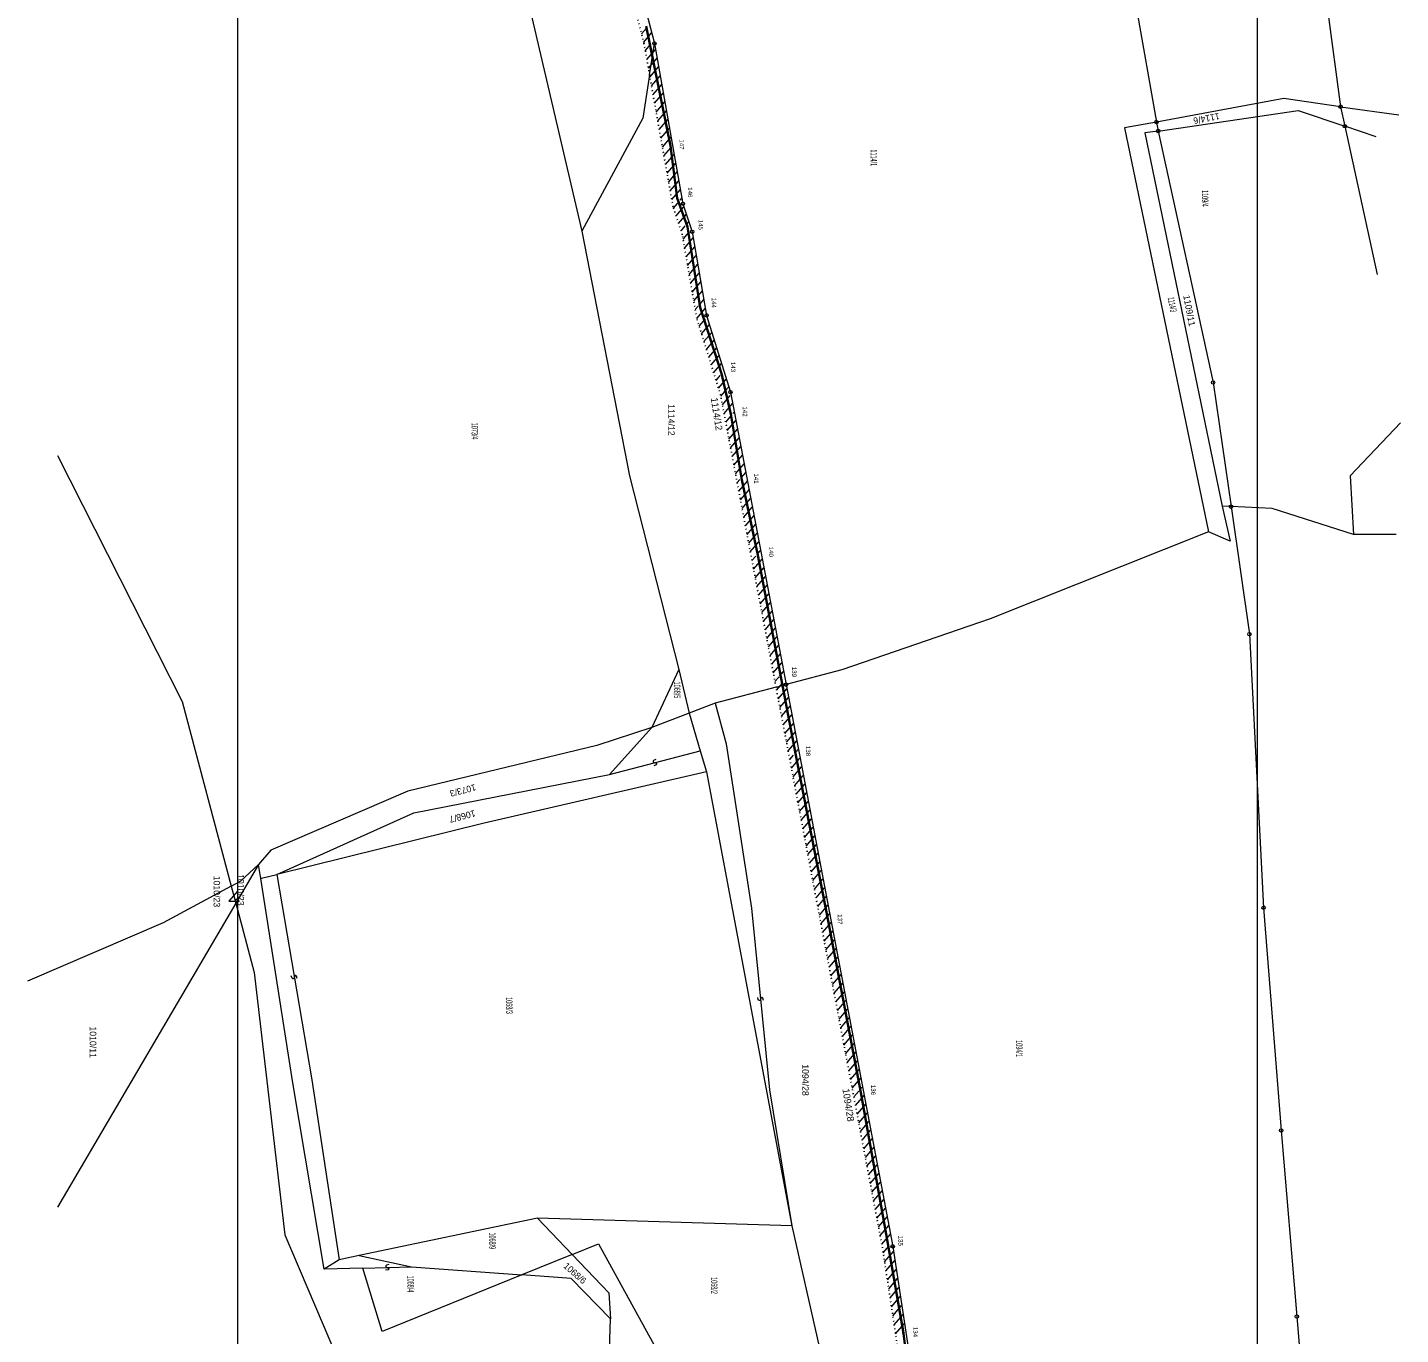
# Model space of a CAD drawing. Extents: x -687355 to -686912, y -958376 to -957235.
# Drawn here: x -687349.1 to -686949.3, y -958143.7 to -957763.2 of the extents above; entities that cross this region are included whole.
import ezdxf
from ezdxf.enums import TextEntityAlignment as Align

# ---------------------------------------------------------------- set-up
doc = ezdxf.new("R2010")
doc.units = 0
doc.header["$LTSCALE"] = 0.76
doc.linetypes.add('DOTTED', pattern=[1.5, 0.3, -1.2])
for name, color, linetype, lineweight in [('1', 7, 'Continuous', 13), ('16', 7, 'Continuous', 13), ('2', 7, 'Continuous', 13), ('28', 7, 'Continuous', 13)]:
    doc.layers.add(name, color=color, linetype=linetype, lineweight=lineweight)
doc.layers.add('14', color=7, linetype='Continuous')

msp = doc.modelspace()

# ---------------------------------------------------------------- linework, layer by layer
at = {"layer": '1', "linetype": 'DOTTED', "lineweight": 25}
for p, q in [((-687169.6, -957767.785), (-687196.769, -957663.253)), ((-687167.989, -957777), (-687169.6, -957767.785)), ((-687161.144, -957815.361), (-687167.989, -957777)), ((-687158.446, -957823.516), (-687161.144, -957815.361)), ((-687154.257, -957847.827), (-687158.446, -957823.516)), ((-687147.315, -957870.163), (-687154.257, -957847.827)), ((-687131.151, -957955.283), (-687147.315, -957870.163)), ((-687100.153, -958118.538), (-687131.151, -957955.283)), ((-687090.903, -958179.389), (-687100.153, -958118.538))]:
    msp.add_line(p, q, dxfattribs=at)
at = {"layer": '1'}
for p, q in [((-687193.4, -957662.8), (-687166.57, -957767.82)), ((-687220.92, -957680.58), (-687187.67, -957822.53)), ((-687028.25, -957746), (-687020.41, -957790.71)), ((-687170.305, -957765.071), (-687168.904, -957763.43)), ((-687169.692, -957767.432), (-687167.365, -957764.707)), ((-687169.22, -957769.959), (-687167.57, -957768.027)), ((-687166.57, -957767.82), (-687158.27, -957814.5)), ((-687168.773, -957772.515), (-687166.258, -957769.571)), ((-687168.326, -957775.072), (-687165.805, -957772.12)), ((-687167.877, -957777.626), (-687165.352, -957774.669)), ((-687167.989, -957777), (-687169.94, -957789.62)), ((-687167.423, -957780.173), (-687164.898, -957777.218)), ((-687166.968, -957782.72), (-687164.445, -957779.766)), ((-687166.514, -957785.268), (-687163.992, -957782.315)), ((-687166.059, -957787.815), (-687163.539, -957784.864)), ((-687165.605, -957790.363), (-687163.086, -957787.413)), ((-686966.78, -957786.25), (-686949.85, -957788.66)), ((-687169.94, -957789.62), (-687187.67, -957822.53)), ((-687165.15, -957792.91), (-687162.632, -957789.962)), ((-687164.696, -957795.457), (-687162.179, -957792.511)), ((-687020.41, -957790.71), (-687019.9, -957793.33)), ((-686956.43, -957795.03), (-686965.54, -957791.95)), ((-687164.241, -957798.005), (-687161.726, -957795.06)), ((-687019.9, -957793.33), (-687003.91, -957866.54)), ((-687163.787, -957800.552), (-687161.787, -957798.211)), ((-687163.332, -957803.099), (-687160.82, -957800.158)), ((-687162.878, -957805.647), (-687160.366, -957802.706)), ((-687162.423, -957808.194), (-687159.913, -957805.255)), ((-687161.969, -957810.742), (-687159.46, -957807.804)), ((-687161.514, -957813.289), (-687159.007, -957810.353)), ((-687159.064, -957813.5), (-687158.554, -957812.902)), ((-687161.007, -957815.775), (-687159.27, -957813.74)), ((-687160.273, -957817.995), (-687158.142, -957815.5)), ((-687159.539, -957820.214), (-687157.261, -957817.548)), ((-687157.225, -957820.585), (-687156.526, -957819.767)), ((-687158.804, -957822.434), (-687157.566, -957820.985)), ((-687158.22, -957824.829), (-687156.57, -957822.897)), ((-687157.778, -957827.392), (-687155.261, -957824.445)), ((-687157.337, -957829.954), (-687154.82, -957827.007)), ((-687156.895, -957832.517), (-687154.378, -957829.569)), ((-687156.453, -957835.08), (-687153.936, -957832.132)), ((-687156.012, -957837.642), (-687153.494, -957834.694)), ((-687155.57, -957840.205), (-687153.052, -957837.256)), ((-687155.129, -957842.767), (-687152.61, -957839.818)), ((-687154.687, -957845.33), (-687153.813, -957844.306)), ((-687153.639, -957844.103), (-687152.168, -957842.38)), ((-687154.239, -957847.885), (-687151.726, -957844.942)), ((-687153.537, -957850.142), (-687151.716, -957848.01)), ((-687151.37, -957847.01), (-687144.43, -957869.34)), ((-687152.836, -957852.4), (-687150.532, -957849.703)), ((-687152.134, -957854.658), (-687149.831, -957851.961)), ((-687151.432, -957856.916), (-687149.129, -957854.219)), ((-687150.73, -957859.174), (-687148.427, -957856.477)), ((-687150.029, -957861.432), (-687147.725, -957858.735)), ((-687149.327, -957863.69), (-687147.024, -957860.993)), ((-687148.625, -957865.948), (-687147.442, -957864.562)), ((-687147.923, -957868.206), (-687145.62, -957865.509)), ((-687147.251, -957870.498), (-687145.43, -957868.365)), ((-687145.408, -957868.34), (-687144.918, -957867.767)), ((-687003.91, -957866.54), (-686998.68, -957902.7)), ((-687146.773, -957873.018), (-687144.486, -957870.34)), ((-687146.295, -957875.537), (-687143.806, -957872.623)), ((-687144.43, -957869.34), (-687128.25, -957954.52)), ((-687145.816, -957878.056), (-687144.358, -957876.349)), ((-687143.697, -957875.575), (-687143.327, -957875.142)), ((-687145.338, -957880.576), (-687142.849, -957877.662)), ((-687144.859, -957883.095), (-687142.37, -957880.181)), ((-687144.381, -957885.615), (-687141.892, -957882.7)), ((-687143.902, -957888.134), (-687141.413, -957885.219)), ((-687143.424, -957890.653), (-687140.935, -957887.739)), ((-687142.946, -957893.173), (-687140.456, -957890.258)), ((-687141.267, -957894.286), (-687139.978, -957892.777)), ((-687142.467, -957895.692), (-687141.667, -957894.756)), ((-687141.989, -957898.211), (-687139.499, -957895.296)), ((-687141.51, -957900.731), (-687139.02, -957897.816)), ((-687141.032, -957903.25), (-687138.542, -957900.335)), ((-687140.553, -957905.77), (-687138.063, -957902.854)), ((-686998.68, -957902.7), (-687001.22, -957902.6)), ((-686998.68, -957902.7), (-686993.32, -957939.83)), ((-687140.075, -957908.289), (-687137.585, -957905.373)), ((-687139.597, -957910.808), (-687137.106, -957907.893)), ((-687139.118, -957913.328), (-687136.628, -957910.412)), ((-686950.64, -957910.79), (-686963, -957910.76)), ((-687138.64, -957915.847), (-687136.149, -957912.931)), ((-687136.355, -957916.251), (-687135.671, -957915.45)), ((-687138.161, -957918.366), (-687137.063, -957917.081)), ((-687137.683, -957920.886), (-687135.192, -957917.97)), ((-687137.204, -957923.405), (-687134.714, -957920.489)), ((-687136.726, -957925.924), (-687134.235, -957923.008)), ((-687136.248, -957928.444), (-687133.757, -957925.527)), ((-687135.769, -957930.963), (-687133.278, -957928.047)), ((-687135.291, -957933.483), (-687132.8, -957930.566)), ((-687134.812, -957936.002), (-687132.321, -957933.085)), ((-687134.334, -957938.521), (-687131.842, -957935.604)), ((-687133.855, -957941.041), (-687131.364, -957938.124)), ((-687133.377, -957943.56), (-687130.885, -957940.643)), ((-686993.32, -957939.83), (-686989.2, -958019.47)), ((-687132.899, -957946.079), (-687130.407, -957943.162)), ((-687132.42, -957948.599), (-687129.928, -957945.681)), ((-687131.942, -957951.118), (-687129.45, -957948.201)), ((-687159.43, -957950.14), (-687167.34, -957967)), ((-687131.463, -957953.637), (-687130.262, -957952.231)), ((-687130.143, -957952.092), (-687128.971, -957950.72)), ((-687112.04, -957950.25), (-687128.25, -957954.52)), ((-687131.151, -957955.283), (-687148.92, -957959.96)), ((-687130.985, -957956.157), (-687129.25, -957954.125)), ((-687130.506, -957958.676), (-687128.014, -957955.758)), ((-687148.92, -957959.96), (-687156.44, -957962.83)), ((-687130.028, -957961.196), (-687127.536, -957958.278)), ((-687129.55, -957963.715), (-687127.057, -957960.797)), ((-687156.44, -957962.83), (-687167.34, -957967)), ((-687129.071, -957966.235), (-687126.579, -957963.316)), ((-687179.65, -957980.68), (-687167.34, -957967)), ((-687128.593, -957968.754), (-687126.1, -957965.836)), ((-687128.115, -957971.273), (-687125.622, -957968.355)), ((-687127.636, -957973.793), (-687125.144, -957970.874)), ((-687179.65, -957980.68), (-687153.22, -957973.76)), ((-687127.158, -957976.312), (-687126.087, -957975.059)), ((-687126.679, -957978.832), (-687124.187, -957975.913)), ((-687125.169, -957973.984), (-687124.665, -957973.394)), ((-687126.201, -957981.351), (-687123.708, -957978.432)), ((-687125.723, -957983.871), (-687123.23, -957980.952)), ((-687125.244, -957986.39), (-687122.751, -957983.471)), ((-687124.766, -957988.91), (-687122.273, -957985.99)), ((-687124.288, -957991.429), (-687121.794, -957988.51)), ((-687123.809, -957993.948), (-687121.316, -957991.029)), ((-687123.331, -957996.468), (-687120.837, -957993.548)), ((-687122.852, -957998.987), (-687120.359, -957996.068)), ((-687122.374, -958001.507), (-687119.881, -957998.587)), ((-687121.896, -958004.026), (-687119.402, -958001.107)), ((-687121.417, -958006.546), (-687118.924, -958003.626)), ((-687281.19, -958010.95), (-687281.83, -958006.9)), ((-687120.939, -958009.065), (-687118.445, -958006.145)), ((-687120.461, -958011.584), (-687117.967, -958008.665)), ((-687119.982, -958014.104), (-687117.488, -958011.184)), ((-687287.95, -958014.69), (-687290.43, -958017.52)), ((-687119.504, -958016.623), (-687117.01, -958013.703)), ((-687119.025, -958019.143), (-687116.531, -958016.223)), ((-687288.45, -958018.19), (-687340.4, -958106.69)), ((-687118.547, -958021.662), (-687116.053, -958018.742)), ((-686989.2, -958019.47), (-686984.09, -958084.32)), ((-687118.069, -958024.182), (-687115.574, -958021.261)), ((-687117.59, -958026.701), (-687115.096, -958023.781)), ((-687117.112, -958029.22), (-687114.618, -958026.3)), ((-687116.634, -958031.74), (-687114.139, -958028.819)), ((-687116.155, -958034.259), (-687113.661, -958031.339)), ((-687115.677, -958036.779), (-687113.182, -958033.858)), ((-687115.198, -958039.298), (-687112.704, -958036.377)), ((-687114.72, -958041.818), (-687112.225, -958038.897)), ((-687114.242, -958044.337), (-687111.747, -958041.416)), ((-687113.763, -958046.856), (-687111.268, -958043.935)), ((-687113.285, -958049.376), (-687110.79, -958046.455)), ((-687112.807, -958051.895), (-687110.312, -958048.974)), ((-687112.328, -958054.415), (-687109.833, -958051.493)), ((-687111.85, -958056.934), (-687109.355, -958054.013)), ((-687111.371, -958059.454), (-687108.876, -958056.532)), ((-687110.893, -958061.973), (-687108.398, -958059.051)), ((-687110.415, -958064.492), (-687107.919, -958061.571)), ((-687109.936, -958067.012), (-687107.441, -958064.09)), ((-687109.458, -958069.531), (-687106.962, -958066.609)), ((-687108.98, -958072.051), (-687106.484, -958069.129)), ((-687106.915, -958072.713), (-687106.005, -958071.648)), ((-687108.501, -958074.57), (-687107.093, -958072.922)), ((-687108.023, -958077.09), (-687105.527, -958074.167)), ((-687107.544, -958079.609), (-687105.049, -958076.687)), ((-687107.066, -958082.128), (-687104.57, -958079.206)), ((-687106.588, -958084.648), (-687104.092, -958081.725)), ((-687106.109, -958087.167), (-687103.613, -958084.245)), ((-686984.09, -958084.32), (-686979.52, -958138.48)), ((-687105.631, -958089.687), (-687103.135, -958086.764)), ((-687105.153, -958092.206), (-687102.656, -958089.284)), ((-687104.674, -958094.726), (-687102.178, -958091.803)), ((-687104.196, -958097.245), (-687101.699, -958094.322)), ((-687103.717, -958099.765), (-687101.221, -958096.842)), ((-687103.239, -958102.284), (-687100.742, -958099.361)), ((-687102.761, -958104.803), (-687100.264, -958101.88)), ((-687102.282, -958107.323), (-687099.786, -958104.4)), ((-687101.804, -958109.842), (-687099.307, -958106.919)), ((-687101.325, -958112.362), (-687098.829, -958109.438)), ((-687100.847, -958114.881), (-687098.35, -958111.958)), ((-687100.369, -958117.401), (-687097.872, -958114.477)), ((-687099.935, -958119.972), (-687098.19, -958117.929)), ((-687099.537, -958122.586), (-687096.961, -958119.57)), ((-687251.42, -958124.38), (-687262.69, -958124.68)), ((-687251.42, -958124.38), (-687237.26, -958124.01)), ((-687099.14, -958125.201), (-687096.564, -958122.184)), ((-687098.743, -958127.815), (-687096.167, -958124.799)), ((-687098.345, -958130.429), (-687095.769, -958127.413)), ((-687097.948, -958133.043), (-687095.372, -958130.027)), ((-687097.551, -958135.658), (-687094.975, -958132.642)), ((-687097.153, -958138.272), (-687094.577, -958135.256)), ((-687096.756, -958140.886), (-687094.18, -958137.87)), ((-687096.358, -958143.501), (-687093.782, -958140.484)), ((-686979.52, -958138.48), (-686976.35, -958176.02))]:
    msp.add_line(p, q, dxfattribs=at)
for points in [[(-687287.96, -957310.331), (-687287.96, -958310.331), (-686990.96, -958310.331), (-686990.96, -957310.331)], [(-687161.778, -957797.511), (-687161.781, -957797.711), (-687161.981, -957797.708), (-687161.978, -957797.508)], [(-687159.858, -957812.811), (-687159.861, -957813.011), (-687160.061, -957813.008), (-687160.058, -957812.808)], [(-687156.868, -957821.091), (-687156.871, -957821.291), (-687157.071, -957821.288), (-687157.068, -957821.088)], [(-687153.118, -957844.611), (-687153.121, -957844.811), (-687153.321, -957844.808), (-687153.318, -957844.608)], [(-687146.888, -957863.871), (-687146.891, -957864.071), (-687147.091, -957864.068), (-687147.088, -957863.868)], [(-687144.198, -957875.651), (-687144.201, -957875.851), (-687144.401, -957875.848), (-687144.398, -957875.648)], [(-687140.968, -957894.791), (-687140.971, -957894.991), (-687141.171, -957894.988), (-687141.168, -957894.788)], [(-687136.358, -957916.751), (-687136.361, -957916.951), (-687136.561, -957916.948), (-687136.558, -957916.748)], [(-687129.568, -957952.601), (-687129.571, -957952.801), (-687129.771, -957952.798), (-687129.768, -957952.598)], [(-687125.378, -957974.481), (-687125.381, -957974.681), (-687125.581, -957974.678), (-687125.578, -957974.478)], [(-687115.868, -958023.171), (-687115.871, -958023.371), (-687116.071, -958023.368), (-687116.068, -958023.168)], [(-687106.398, -958073.221), (-687106.401, -958073.421), (-687106.601, -958073.418), (-687106.598, -958073.218)], [(-687098.478, -958117.101), (-687098.481, -958117.301), (-687098.681, -958117.298), (-687098.678, -958117.098)], [(-687093.988, -958143.291), (-687093.991, -958143.491), (-687094.191, -958143.488), (-687094.188, -958143.288)]]:
    msp.add_lwpolyline(points, close=True, dxfattribs=at)
for points in [[(-686985.76, -957644.49), (-686966.78, -957786.25), (-686965.54, -957791.95), (-686956.11, -957835.14)], [(-686966.78, -957786.25), (-686983.35, -957783.9), (-687020.41, -957790.71)], [(-687019.9, -957793.33), (-686979.14, -957787.35), (-686965.54, -957791.95)], [(-687020.41, -957790.71), (-687029.66, -957792.41), (-687005.25, -957910.06), (-687068.79, -957935.37), (-687112.04, -957950.25)], [(-687019.9, -957793.33), (-687023.73, -957793.89), (-687001.22, -957902.6), (-686998.9, -957912.74), (-687005.25, -957910.06)], [(-687158.27, -957814.5), (-687155.57, -957822.66), (-687151.37, -957847.01)], [(-687187.67, -957822.53), (-687173.85, -957893.76), (-687159.43, -957950.14)], [(-686949.33, -957878.3), (-686963.99, -957893.77), (-686963, -957910.76)], [(-687340.35, -957887.8), (-687304.03, -957959.4), (-687289.77, -958013.23)], [(-686963, -957910.76), (-686986.69, -957903.2), (-686998.68, -957902.7)], [(-687159.43, -957950.14), (-687156.44, -957962.83), (-687153.22, -957973.76), (-687151.4, -957979.95), (-687126.55, -958112.05)], [(-687128.25, -957954.52), (-687097.19, -958118.07), (-687087.95, -958178.86)], [(-687148.92, -957959.96), (-687145.67, -957971.79), (-687138.27, -958019.65), (-687133.01, -958072.48), (-687126.55, -958112.05)], [(-687167.34, -957967), (-687183.33, -957972.2), (-687238.37, -957985.54), (-687278.29, -958002.75), (-687281.83, -958006.9)], [(-687166.153, -957976.319), (-687166.805, -957976.593), (-687166.948, -957976.837), (-687166.897, -957977.031), (-687166.653, -957977.173), (-687166.216, -957977.266), (-687165.972, -957977.408), (-687165.921, -957977.602), (-687166.064, -957977.846), (-687166.716, -957978.12)], [(-687151.4, -957979.95), (-687216.09, -957994.84), (-687276.52, -958009.83)], [(-687276.52, -958009.83), (-687236.64, -957991.89), (-687179.65, -957980.68)], [(-687289.77, -958013.23), (-687287.04, -958011.77), (-687281.83, -958006.9), (-687288.45, -958018.19)], [(-687252.52, -958120.76), (-687258.33, -958121.99), (-687262.69, -958124.68), (-687271.83, -958070.43), (-687281.19, -958010.95), (-687280.54, -958010.79), (-687276.52, -958009.83)], [(-687276.52, -958009.83), (-687266.29, -958069.56), (-687258.33, -958121.99)], [(-687289.77, -958013.23), (-687309.59, -958023.89), (-687349.1, -958040.84)], [(-687289.77, -958013.23), (-687288.45, -958018.19), (-687283.12, -958038.32), (-687274.12, -958114.74), (-687252.46, -958165.73), (-687201.83, -958253.91)], [(-687270.532, -958040.052), (-687270.748, -958039.379), (-687270.979, -958039.216), (-687271.176, -958039.25), (-687271.34, -958039.48), (-687271.469, -958039.909), (-687271.633, -958040.139), (-687271.83, -958040.173), (-687272.061, -958040.01), (-687272.277, -958039.337)], [(-687134.794, -958046.483), (-687134.963, -958045.796), (-687135.182, -958045.617), (-687135.381, -958045.637), (-687135.56, -958045.856), (-687135.719, -958046.273), (-687135.898, -958046.492), (-687136.097, -958046.512), (-687136.316, -958046.333), (-687136.485, -958045.646)], [(-687126.55, -958112.05), (-687200.63, -958109.82), (-687252.52, -958120.76)], [(-687200.63, -958109.82), (-687190.47, -958120.44), (-687205.15, -958126.39)], [(-687126.55, -958112.05), (-687118.53, -958147.73), (-687109.71, -958175.34), (-687103.96, -958208.19), (-687099.17, -958221.16)], [(-687252.52, -958120.76), (-687237.26, -958124.01), (-687205.15, -958126.39)], [(-687190.47, -958120.44), (-687182.85, -958117.36), (-687157.48, -958163.42)], [(-687190.47, -958120.44), (-687179.8, -958131.58), (-687179.37, -958139.16)], [(-687205.15, -958126.39), (-687245.82, -958142.85), (-687251.42, -958124.38)], [(-687243.861, -958123.382), (-687244.558, -958123.5), (-687244.752, -958123.705), (-687244.747, -958123.905), (-687244.542, -958124.1), (-687244.137, -958124.289), (-687243.932, -958124.484), (-687243.927, -958124.684), (-687244.121, -958124.889), (-687244.818, -958125.007)], [(-687179.37, -958139.16), (-687190.79, -958127.45), (-687205.15, -958126.39)], [(-687157.48, -958163.42), (-687167.35, -958172.3), (-687180.29, -958168.41), (-687179.37, -958139.16)]]:
    msp.add_lwpolyline(points, dxfattribs=at)
for centre, radius in [((-687166.57, -957767.82), 0.5), ((-687166.57, -957767.82), 0.01), ((-686966.78, -957786.25), 0.5), ((-686966.78, -957786.25), 0.01), ((-687020.41, -957790.71), 0.5), ((-687020.41, -957790.71), 0.01), ((-687019.9, -957793.33), 0.5), ((-686965.54, -957791.95), 0.5), ((-686965.54, -957791.95), 0.01), ((-687019.9, -957793.33), 0.01), ((-687158.27, -957814.5), 0.5), ((-687158.27, -957814.5), 0.01), ((-687155.57, -957822.66), 0.5), ((-687155.57, -957822.66), 0.01), ((-687151.37, -957847.01), 0.5), ((-687151.37, -957847.01), 0.01), ((-687144.43, -957869.34), 0.5), ((-687003.91, -957866.54), 0.5), ((-687003.91, -957866.54), 0.01), ((-687144.43, -957869.34), 0.01), ((-686998.68, -957902.7), 0.5), ((-686998.68, -957902.7), 0.01), ((-686993.32, -957939.83), 0.5), ((-686993.32, -957939.83), 0.01), ((-687128.25, -957954.52), 0.5), ((-687128.25, -957954.52), 0.01), ((-686989.2, -958019.47), 0.5), ((-686989.2, -958019.47), 0.01), ((-686984.09, -958084.32), 0.5), ((-686984.09, -958084.32), 0.01), ((-687097.19, -958118.07), 0.5), ((-687097.19, -958118.07), 0.01), ((-686979.52, -958138.48), 0.5), ((-686979.52, -958138.48), 0.01)]:
    msp.add_circle(centre, radius, dxfattribs=at)
at = {"layer": '16'}
msp.add_line((-687287.43, -958017.52), (-687288.43, -958018.02), dxfattribs=at)
msp.add_lwpolyline([(-687290.43, -958017.52), (-687287.43, -958017.52), (-687288.43, -958017.02)], dxfattribs=at)
at = {"layer": '2'}
for p, q in [((-687167.989, -957777), (-687166.57, -957767.82)), ((-687131.151, -957955.283), (-687128.25, -957954.52))]:
    msp.add_line(p, q, dxfattribs=at)
at = {"layer": '2', "lineweight": 35}
msp.add_lwpolyline([(-687079.355, -958217.582), (-687078.27, -958216.4), (-687079.21, -958212.07), (-687089.1, -958178.68), (-687091.56, -958163.84), (-687094.09, -958143.39), (-687098.58, -958117.2), (-687106.5, -958073.32), (-687115.97, -958023.27), (-687125.48, -957974.58), (-687129.67, -957952.7), (-687136.46, -957916.85), (-687141.07, -957894.89), (-687144.3, -957875.75), (-687146.99, -957863.97), (-687153.22, -957844.71), (-687156.97, -957821.19), (-687159.96, -957812.91), (-687161.88, -957797.61), (-687168.94, -957762.83)], dxfattribs=at)
at = {"layer": '28'}
for centre, radius in [((-687166.57, -957767.82), 0.5), ((-687166.57, -957767.82), 0.01), ((-686966.78, -957786.25), 0.5), ((-686966.78, -957786.25), 0.01), ((-687020.41, -957790.71), 0.5), ((-687020.41, -957790.71), 0.01), ((-687019.9, -957793.33), 0.5), ((-686965.54, -957791.95), 0.5), ((-686965.54, -957791.95), 0.01), ((-687019.9, -957793.33), 0.01), ((-687158.27, -957814.5), 0.5), ((-687158.27, -957814.5), 0.01), ((-687155.57, -957822.66), 0.5), ((-687155.57, -957822.66), 0.01), ((-687151.37, -957847.01), 0.5), ((-687151.37, -957847.01), 0.01), ((-687144.43, -957869.34), 0.5), ((-687003.91, -957866.54), 0.5), ((-687003.91, -957866.54), 0.01), ((-687144.43, -957869.34), 0.01), ((-686998.68, -957902.7), 0.5), ((-686998.68, -957902.7), 0.01), ((-686993.32, -957939.83), 0.5), ((-686993.32, -957939.83), 0.01), ((-687128.25, -957954.52), 0.5), ((-687128.25, -957954.52), 0.01), ((-686989.2, -958019.47), 0.5), ((-686989.2, -958019.47), 0.01), ((-686984.09, -958084.32), 0.5), ((-686984.09, -958084.32), 0.01), ((-687097.19, -958118.07), 0.5), ((-687097.19, -958118.07), 0.01), ((-686979.52, -958138.48), 0.5), ((-686979.52, -958138.48), 0.01)]:
    msp.add_circle(centre, radius, dxfattribs=at)

# ---------------------------------------------------------------- texts
at = {"layer": '1', "width": 0.9}
for s, p in [('147', (-687159.257, -957795.743)), ('146', (-687156.814, -957809.698)), ('145', (-687153.716, -957819.128)), ('144', (-687149.862, -957841.842)), ('143', (-687144.293, -957860.528)), ('142', (-687140.845, -957873.503)), ('141', (-687137.542, -957893.016)), ('140', (-687133.205, -957914.353)), ('139', (-687126.495, -957949.318)), ('138', (-687122.434, -957972.359)), ('137', (-687113.176, -958021.365)), ('136', (-687103.471, -958071.043)), ('135', (-687095.521, -958114.956)), ('134', (-687091.185, -958141.49))]:
    msp.add_text(s, height=1.3, rotation=270, dxfattribs=at).set_placement(p)
at = {"layer": '1'}
for s, p in [('1114/12', (-687150.175, -957871.111)), ('1094/28', (-687111.84, -958072.303))]:
    msp.add_text(s, height=2, rotation=279, dxfattribs=at).set_placement(p)
at = {"layer": '14'}
for s, rotation, p in [('1114/6', 190.8, (-687005.994, -957788.757)), ('1109/11', 280.8, (-687011.746, -957845.794)), ('1114/12', 270, (-687162.553, -957877.45)), ('1073/3', 194.4, (-687222.558, -957984.409)), ('1068/7', 194.4, (-687222.713, -957991.968)), ('1010/23', 270, (-687287.95, -958014.269)), ('1010/11', 270, (-687330.96, -958058.619)), ('1094/28', 270, (-687123.538, -958069.64)), ('1068/6', 318.6, (-687190.315, -958126.619))]:
    msp.add_text(s, height=1.9, rotation=rotation, dxfattribs=at).set_placement(p, align=Align.CENTER)
for s, rotation, width, p in [('1114/1', 270, 0.5, (-687103.63, -957801.125)), ('1109/4', 270, 0.5, (-687007.155, -957812.962)), ('1114/3', 280.8, 0.45, (-687016.718, -957844.056)), ('1073/4', 270, 0.5, (-687219.811, -957880.719)), ('1068/5', 270, 0.5, (-687160.89, -957956.068)), ('1068/3', 270, 0.5, (-687209.772, -958047.947)), ('1094/1', 270, 0.5, (-687061.272, -958060.474)), ('1068/9', 270, 0.5, (-687214.671, -958116.458)), ('1068/4', 270, 0.5, (-687238.474, -958129.008)), ('1068/2', 270, 0.5, (-687150.101, -958129.479))]:
    msp.add_text(s, height=1.9, rotation=rotation, dxfattribs=dict(at, width=width)).set_placement(p, align=Align.CENTER)
at = {"layer": '16'}
msp.add_text('1010/23', height=1.9, rotation=270, dxfattribs=at).set_placement((-687294.91, -958019.329), align=Align.RIGHT)

doc.saveas('drawing.dxf')
